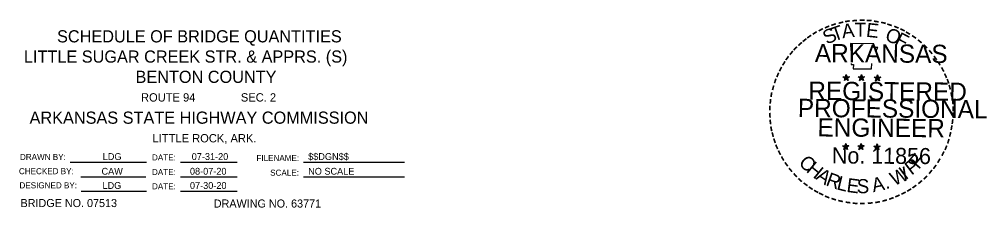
# Model space of a CAD drawing. Extents: x 1667526.8 to 1667564.8, y 551427.6 to 551446.9.
# Drawn here: x 1667548.89 to 1667564.79, y 551427.59 to 551430.69 of the extents above; entities that cross this region are included whole.
import ezdxf

# ---------------------------------------------------------------- set-up
doc = ezdxf.new("R2010")
doc.units = 0
for name, color, linetype in [('Level 4', 7, 'Continuous'), ('Level 49', 7, 'Continuous'), ('Level 50', 7, 'Continuous')]:
    doc.layers.add(name, color=color, linetype=linetype)

msp = doc.modelspace()

# ---------------------------------------------------------------- linework, layer by layer
at = {"layer": 'Level 4'}
for p, q in [((1667549.721, 551428.342), (1667550.978, 551428.342)), ((1667551.535, 551428.342), (1667552.471, 551428.342)), ((1667553.561, 551428.342), (1667555.22, 551428.342)), ((1667549.898, 551428.1), (1667550.968, 551428.1)), ((1667551.535, 551428.1), (1667552.471, 551428.1)), ((1667553.561, 551428.1), (1667555.22, 551428.1)), ((1667549.906, 551427.866), (1667550.975, 551427.866)), ((1667551.535, 551427.866), (1667552.471, 551427.866))]:
    msp.add_line(p, q, dxfattribs=at)
at = {"layer": 'Level 49'}
for p, q in [((1667562.43, 551429.747), (1667562.484, 551429.73)), ((1667562.43, 551429.747), (1667562.469, 551429.745)), ((1667562.43, 551429.747), (1667562.469, 551429.743)), ((1667562.43, 551429.747), (1667562.466, 551429.737)), ((1667562.43, 551429.747), (1667562.466, 551429.732)), ((1667562.43, 551429.747), (1667562.466, 551429.73)), ((1667562.43, 551429.747), (1667562.466, 551429.724)), ((1667562.453, 551429.685), (1667562.484, 551429.73)), ((1667562.453, 551429.685), (1667562.466, 551429.728)), ((1667562.453, 551429.685), (1667562.469, 551429.722)), ((1667562.453, 551429.685), (1667562.471, 551429.721)), ((1667562.453, 551429.685), (1667562.477, 551429.717)), ((1667562.453, 551429.685), (1667562.484, 551429.717)), ((1667562.453, 551429.685), (1667562.484, 551429.713)), ((1667562.484, 551429.787), (1667562.477, 551429.747)), ((1667562.484, 551429.787), (1667562.477, 551429.75)), ((1667562.484, 551429.787), (1667562.48, 551429.75)), ((1667562.484, 551429.73), (1667562.484, 551429.787)), ((1667562.484, 551429.787), (1667562.493, 551429.747)), ((1667562.484, 551429.787), (1667562.491, 551429.75)), ((1667562.484, 551429.787), (1667562.486, 551429.75)), ((1667562.536, 551429.747), (1667562.484, 551429.73)), ((1667562.515, 551429.684), (1667562.484, 551429.73)), ((1667562.515, 551429.684), (1667562.484, 551429.717)), ((1667562.515, 551429.684), (1667562.484, 551429.713)), ((1667562.536, 551429.747), (1667562.488, 551429.743)), ((1667562.515, 551429.684), (1667562.488, 551429.717)), ((1667562.536, 551429.747), (1667562.493, 551429.739)), ((1667562.536, 551429.747), (1667562.493, 551429.735)), ((1667562.515, 551429.684), (1667562.493, 551429.728)), ((1667562.515, 551429.684), (1667562.493, 551429.722)), ((1667562.515, 551429.684), (1667562.499, 551429.73)), ((1667562.536, 551429.747), (1667562.501, 551429.735)), ((1667562.536, 551429.747), (1667562.506, 551429.732)), ((1667562.536, 551429.747), (1667562.508, 551429.73)), ((1667562.68, 551429.745), (1667562.734, 551429.73)), ((1667562.68, 551429.745), (1667562.719, 551429.743)), ((1667562.68, 551429.745), (1667562.719, 551429.739)), ((1667562.68, 551429.745), (1667562.719, 551429.737)), ((1667562.68, 551429.745), (1667562.717, 551429.73)), ((1667562.68, 551429.745), (1667562.717, 551429.728)), ((1667562.68, 551429.745), (1667562.717, 551429.722)), ((1667562.702, 551429.684), (1667562.734, 551429.73)), ((1667562.702, 551429.684), (1667562.719, 551429.724)), ((1667562.702, 551429.684), (1667562.719, 551429.722)), ((1667562.702, 551429.684), (1667562.721, 551429.721)), ((1667562.702, 551429.684), (1667562.726, 551429.715)), ((1667562.702, 551429.684), (1667562.734, 551429.715)), ((1667562.702, 551429.684), (1667562.734, 551429.713)), ((1667562.734, 551429.784), (1667562.726, 551429.745)), ((1667562.734, 551429.784), (1667562.726, 551429.747)), ((1667562.734, 551429.784), (1667562.728, 551429.747)), ((1667562.734, 551429.73), (1667562.734, 551429.784)), ((1667562.734, 551429.784), (1667562.743, 551429.745)), ((1667562.734, 551429.784), (1667562.741, 551429.747)), ((1667562.734, 551429.784), (1667562.736, 551429.747)), ((1667562.786, 551429.745), (1667562.734, 551429.73)), ((1667562.765, 551429.684), (1667562.734, 551429.73)), ((1667562.765, 551429.684), (1667562.734, 551429.715)), ((1667562.765, 551429.684), (1667562.734, 551429.713)), ((1667562.786, 551429.745), (1667562.739, 551429.743)), ((1667562.765, 551429.684), (1667562.739, 551429.715)), ((1667562.786, 551429.745), (1667562.743, 551429.737)), ((1667562.786, 551429.745), (1667562.743, 551429.735)), ((1667562.765, 551429.684), (1667562.743, 551429.728)), ((1667562.765, 551429.684), (1667562.743, 551429.721)), ((1667562.765, 551429.684), (1667562.749, 551429.728)), ((1667562.786, 551429.745), (1667562.75, 551429.732)), ((1667562.786, 551429.745), (1667562.756, 551429.73)), ((1667562.786, 551429.745), (1667562.758, 551429.728)), ((1667562.945, 551429.743), (1667562.998, 551429.724)), ((1667562.945, 551429.743), (1667562.987, 551429.737)), ((1667562.945, 551429.743), (1667562.984, 551429.735)), ((1667562.945, 551429.743), (1667562.984, 551429.732)), ((1667562.945, 551429.743), (1667562.982, 551429.728)), ((1667562.945, 551429.743), (1667562.982, 551429.722)), ((1667562.945, 551429.743), (1667562.982, 551429.722)), ((1667562.965, 551429.682), (1667562.998, 551429.724)), ((1667562.965, 551429.682), (1667562.984, 551429.722)), ((1667562.965, 551429.682), (1667562.987, 551429.717)), ((1667562.965, 551429.682), (1667562.987, 551429.715)), ((1667562.965, 551429.682), (1667562.998, 551429.715)), ((1667562.965, 551429.682), (1667562.995, 551429.713)), ((1667562.965, 551429.682), (1667563.002, 551429.708)), ((1667562.998, 551429.78), (1667562.989, 551429.745)), ((1667562.998, 551429.78), (1667562.995, 551429.743)), ((1667562.998, 551429.78), (1667562.995, 551429.743)), ((1667562.998, 551429.724), (1667562.998, 551429.78)), ((1667562.998, 551429.78), (1667563.009, 551429.743)), ((1667562.998, 551429.78), (1667563.006, 551429.743)), ((1667562.998, 551429.78), (1667563.002, 551429.743)), ((1667563.05, 551429.743), (1667562.998, 551429.724)), ((1667563.028, 551429.682), (1667562.998, 551429.724)), ((1667563.028, 551429.682), (1667562.998, 551429.715)), ((1667563.028, 551429.682), (1667562.998, 551429.708)), ((1667563.05, 551429.743), (1667563.004, 551429.737)), ((1667563.028, 551429.682), (1667563.004, 551429.713)), ((1667563.05, 551429.743), (1667563.009, 551429.735)), ((1667563.05, 551429.743), (1667563.009, 551429.73)), ((1667563.028, 551429.682), (1667563.009, 551429.722)), ((1667563.028, 551429.682), (1667563.009, 551429.717)), ((1667563.028, 551429.682), (1667563.013, 551429.722)), ((1667563.05, 551429.743), (1667563.017, 551429.728)), ((1667563.05, 551429.743), (1667563.019, 551429.728)), ((1667563.05, 551429.743), (1667563.024, 551429.724)), ((1667562.423, 551428.611), (1667562.477, 551428.594)), ((1667562.423, 551428.611), (1667562.462, 551428.609)), ((1667562.423, 551428.611), (1667562.46, 551428.603)), ((1667562.423, 551428.611), (1667562.46, 551428.603)), ((1667562.423, 551428.611), (1667562.46, 551428.596)), ((1667562.423, 551428.611), (1667562.46, 551428.594)), ((1667562.423, 551428.611), (1667562.46, 551428.592)), ((1667562.441, 551428.553), (1667562.477, 551428.594)), ((1667562.441, 551428.553), (1667562.46, 551428.594)), ((1667562.441, 551428.553), (1667562.462, 551428.587)), ((1667562.441, 551428.553), (1667562.464, 551428.587)), ((1667562.441, 551428.553), (1667562.477, 551428.585)), ((1667562.441, 551428.553), (1667562.469, 551428.581)), ((1667562.441, 551428.553), (1667562.477, 551428.579)), ((1667562.477, 551428.651), (1667562.466, 551428.614)), ((1667562.477, 551428.651), (1667562.469, 551428.611)), ((1667562.477, 551428.651), (1667562.471, 551428.611)), ((1667562.506, 551428.55), (1667562.473, 551428.579)), ((1667562.477, 551428.594), (1667562.477, 551428.651)), ((1667562.477, 551428.651), (1667562.484, 551428.611)), ((1667562.477, 551428.651), (1667562.484, 551428.611)), ((1667562.477, 551428.651), (1667562.477, 551428.611)), ((1667562.528, 551428.611), (1667562.477, 551428.594)), ((1667562.506, 551428.55), (1667562.477, 551428.594)), ((1667562.506, 551428.55), (1667562.477, 551428.581)), ((1667562.506, 551428.55), (1667562.478, 551428.581)), ((1667562.528, 551428.611), (1667562.48, 551428.609)), ((1667562.528, 551428.611), (1667562.484, 551428.603)), ((1667562.528, 551428.611), (1667562.484, 551428.601)), ((1667562.506, 551428.55), (1667562.484, 551428.594)), ((1667562.506, 551428.55), (1667562.484, 551428.587)), ((1667562.528, 551428.611), (1667562.491, 551428.6)), ((1667562.506, 551428.55), (1667562.491, 551428.594)), ((1667562.528, 551428.611), (1667562.495, 551428.596)), ((1667562.528, 551428.611), (1667562.499, 551428.594)), ((1667562.673, 551428.611), (1667562.726, 551428.594)), ((1667562.673, 551428.611), (1667562.712, 551428.607)), ((1667562.673, 551428.611), (1667562.712, 551428.603)), ((1667562.673, 551428.611), (1667562.712, 551428.601)), ((1667562.673, 551428.611), (1667562.71, 551428.596)), ((1667562.673, 551428.611), (1667562.71, 551428.592)), ((1667562.673, 551428.611), (1667562.71, 551428.588)), ((1667562.691, 551428.55), (1667562.726, 551428.594)), ((1667562.691, 551428.55), (1667562.712, 551428.592)), ((1667562.691, 551428.55), (1667562.712, 551428.585)), ((1667562.691, 551428.55), (1667562.713, 551428.585)), ((1667562.691, 551428.55), (1667562.719, 551428.581)), ((1667562.691, 551428.55), (1667562.726, 551428.581)), ((1667562.691, 551428.55), (1667562.726, 551428.577)), ((1667562.726, 551428.648), (1667562.717, 551428.611)), ((1667562.726, 551428.648), (1667562.719, 551428.611)), ((1667562.726, 551428.648), (1667562.721, 551428.611)), ((1667562.756, 551428.55), (1667562.725, 551428.577)), ((1667562.726, 551428.594), (1667562.726, 551428.648)), ((1667562.726, 551428.648), (1667562.734, 551428.609)), ((1667562.726, 551428.648), (1667562.734, 551428.609)), ((1667562.726, 551428.648), (1667562.726, 551428.611)), ((1667562.776, 551428.609), (1667562.726, 551428.594)), ((1667562.756, 551428.55), (1667562.726, 551428.594)), ((1667562.756, 551428.55), (1667562.726, 551428.581)), ((1667562.756, 551428.55), (1667562.728, 551428.581)), ((1667562.776, 551428.609), (1667562.732, 551428.609)), ((1667562.776, 551428.609), (1667562.734, 551428.601)), ((1667562.776, 551428.609), (1667562.734, 551428.601)), ((1667562.756, 551428.55), (1667562.734, 551428.592)), ((1667562.756, 551428.55), (1667562.734, 551428.587)), ((1667562.776, 551428.609), (1667562.741, 551428.596)), ((1667562.756, 551428.55), (1667562.741, 551428.592)), ((1667562.776, 551428.609), (1667562.747, 551428.594)), ((1667562.776, 551428.609), (1667562.749, 551428.592)), ((1667562.937, 551428.607), (1667562.991, 551428.588)), ((1667562.937, 551428.607), (1667562.976, 551428.603)), ((1667562.937, 551428.607), (1667562.976, 551428.6)), ((1667562.937, 551428.607), (1667562.974, 551428.596)), ((1667562.937, 551428.607), (1667562.974, 551428.592)), ((1667562.937, 551428.607), (1667562.972, 551428.588)), ((1667562.937, 551428.607), (1667562.972, 551428.585)), ((1667562.958, 551428.546), (1667562.991, 551428.588)), ((1667562.958, 551428.546), (1667562.974, 551428.588)), ((1667562.958, 551428.546), (1667562.976, 551428.581)), ((1667562.958, 551428.546), (1667562.98, 551428.581)), ((1667562.958, 551428.546), (1667562.984, 551428.577)), ((1667562.958, 551428.546), (1667562.989, 551428.577)), ((1667562.958, 551428.546), (1667562.991, 551428.574)), ((1667562.991, 551428.646), (1667562.982, 551428.607)), ((1667562.991, 551428.646), (1667562.984, 551428.607)), ((1667562.991, 551428.646), (1667562.987, 551428.607)), ((1667563.021, 551428.546), (1667562.989, 551428.577)), ((1667563.021, 551428.546), (1667562.989, 551428.574)), ((1667562.991, 551428.588), (1667562.991, 551428.646)), ((1667562.991, 551428.646), (1667562.998, 551428.607)), ((1667562.991, 551428.646), (1667562.998, 551428.607)), ((1667562.991, 551428.646), (1667562.991, 551428.607)), ((1667563.043, 551428.607), (1667562.991, 551428.588)), ((1667563.021, 551428.546), (1667562.991, 551428.588)), ((1667563.021, 551428.546), (1667562.995, 551428.577)), ((1667563.043, 551428.607), (1667562.996, 551428.603)), ((1667563.043, 551428.607), (1667562.998, 551428.6)), ((1667563.043, 551428.607), (1667562.998, 551428.596)), ((1667563.021, 551428.546), (1667562.998, 551428.581)), ((1667563.021, 551428.546), (1667563.002, 551428.588)), ((1667563.021, 551428.546), (1667563.004, 551428.588)), ((1667563.043, 551428.607), (1667563.009, 551428.594)), ((1667563.043, 551428.607), (1667563.011, 551428.588)), ((1667563.043, 551428.607), (1667563.013, 551428.588))]:
    msp.add_line(p, q, dxfattribs=at)
for points in [[(1667562.552, 551430.294), (1667562.558, 551430.179)], [(1667562.978, 551430.179), (1667563.002, 551430.231), (1667562.932, 551430.231), (1667562.935, 551430.29), (1667562.552, 551430.294)], [(1667562.565, 551429.965), (1667562.567, 551429.95), (1667562.601, 551429.948), (1667562.595, 551429.88), (1667562.897, 551429.878), (1667562.904, 551429.965)], [(1667562.484, 551429.787), (1667562.515, 551429.684), (1667562.43, 551429.747), (1667562.536, 551429.747), (1667562.453, 551429.685), (1667562.484, 551429.787)], [(1667562.734, 551429.784), (1667562.765, 551429.684), (1667562.68, 551429.745), (1667562.786, 551429.745), (1667562.702, 551429.684), (1667562.734, 551429.784)], [(1667562.998, 551429.78), (1667563.028, 551429.682), (1667562.945, 551429.743), (1667563.05, 551429.743), (1667562.965, 551429.682), (1667562.998, 551429.78)], [(1667562.477, 551428.651), (1667562.506, 551428.55), (1667562.423, 551428.611), (1667562.528, 551428.611), (1667562.441, 551428.553), (1667562.477, 551428.651)], [(1667562.726, 551428.648), (1667562.756, 551428.55), (1667562.673, 551428.611), (1667562.776, 551428.609), (1667562.691, 551428.55), (1667562.726, 551428.648)], [(1667562.991, 551428.646), (1667563.021, 551428.546), (1667562.937, 551428.607), (1667563.043, 551428.607), (1667562.958, 551428.546), (1667562.991, 551428.646)]]:
    msp.add_lwpolyline(points, dxfattribs=at)
for centre, radius in [((1667562.483, 551429.73), 0.0258), ((1667562.483, 551429.73), 0.0234), ((1667562.483, 551429.73), 0.0217), ((1667562.483, 551429.73), 0.0199), ((1667562.483, 551429.73), 0.0173), ((1667562.483, 551429.73), 0.0161), ((1667562.483, 551429.73), 0.0149), ((1667562.483, 551429.73), 0.0128), ((1667562.483, 551429.73), 0.0112), ((1667562.483, 551429.73), 0.00931), ((1667562.483, 551429.73), 0.00743), ((1667562.483, 551429.73), 0.00554), ((1667562.483, 551429.73), 0.00444), ((1667562.483, 551429.73), 0.00216), ((1667562.733, 551429.728), 0.0258), ((1667562.733, 551429.728), 0.0234), ((1667562.733, 551429.728), 0.0217), ((1667562.733, 551429.728), 0.0199), ((1667562.733, 551429.728), 0.0173), ((1667562.733, 551429.728), 0.0161), ((1667562.733, 551429.728), 0.0149), ((1667562.733, 551429.728), 0.0128), ((1667562.733, 551429.728), 0.0112), ((1667562.733, 551429.728), 0.00931), ((1667562.733, 551429.728), 0.00743), ((1667562.733, 551429.728), 0.00554), ((1667562.733, 551429.728), 0.00444), ((1667562.733, 551429.728), 0.00216), ((1667562.998, 551429.725), 0.0258), ((1667562.998, 551429.725), 0.0234), ((1667562.998, 551429.725), 0.0217), ((1667562.998, 551429.725), 0.0199), ((1667562.998, 551429.725), 0.0173), ((1667562.998, 551429.725), 0.0161), ((1667562.998, 551429.725), 0.0149), ((1667562.998, 551429.725), 0.0128), ((1667562.998, 551429.725), 0.0112), ((1667562.998, 551429.725), 0.00931), ((1667562.998, 551429.725), 0.00743), ((1667562.998, 551429.725), 0.00554), ((1667562.998, 551429.725), 0.00444), ((1667562.998, 551429.725), 0.00216), ((1667562.475, 551428.595), 0.0258), ((1667562.475, 551428.595), 0.0234), ((1667562.475, 551428.595), 0.0217), ((1667562.475, 551428.595), 0.0199), ((1667562.475, 551428.595), 0.0173), ((1667562.475, 551428.595), 0.0161), ((1667562.475, 551428.595), 0.0149), ((1667562.475, 551428.595), 0.0128), ((1667562.475, 551428.595), 0.0112), ((1667562.475, 551428.595), 0.00931), ((1667562.475, 551428.595), 0.00743), ((1667562.475, 551428.595), 0.00554), ((1667562.475, 551428.595), 0.00444), ((1667562.475, 551428.595), 0.00216), ((1667562.725, 551428.593), 0.0258), ((1667562.725, 551428.593), 0.0234), ((1667562.725, 551428.593), 0.0217), ((1667562.725, 551428.593), 0.0199), ((1667562.725, 551428.593), 0.0173), ((1667562.725, 551428.593), 0.0161), ((1667562.725, 551428.593), 0.0149), ((1667562.725, 551428.593), 0.0128), ((1667562.725, 551428.593), 0.0112), ((1667562.725, 551428.593), 0.00931), ((1667562.725, 551428.593), 0.00743), ((1667562.725, 551428.593), 0.00554), ((1667562.725, 551428.593), 0.00444), ((1667562.725, 551428.593), 0.00216), ((1667562.99, 551428.59), 0.0258), ((1667562.99, 551428.59), 0.0234), ((1667562.99, 551428.59), 0.0217), ((1667562.99, 551428.59), 0.0199), ((1667562.99, 551428.59), 0.0173), ((1667562.99, 551428.59), 0.0161), ((1667562.99, 551428.59), 0.0149), ((1667562.99, 551428.59), 0.0128), ((1667562.99, 551428.59), 0.0112), ((1667562.99, 551428.59), 0.00931), ((1667562.99, 551428.59), 0.00743), ((1667562.99, 551428.59), 0.00554), ((1667562.99, 551428.59), 0.00444), ((1667562.99, 551428.59), 0.00216)]:
    msp.add_circle(centre, radius, dxfattribs=at)

# ---------------------------------------------------------------- texts
at = {"layer": 'Level 4'}
for s, height, rotation, p in [('SCHEDULE OF BRIDGE QUANTITIES', 0.19998, 0.0047, (1667549.507, 551430.313)), ('LITTLE SUGAR CREEK STR. & APPRS. (S)', 0.19998, 0.0047, (1667548.962, 551429.98)), ('BENTON COUNTY', 0.19998, 0.0047, (1667550.797, 551429.647)), ('ROUTE 94', 0.1369, 0.0065, (1667550.887, 551429.34)), ('SEC. 2', 0.1369, 0.0065, (1667552.529, 551429.34)), ('ARKANSAS STATE HIGHWAY COMMISSION', 0.19998, 0.0047, (1667549.055, 551428.975)), ('LITTLE ROCK, ARK.', 0.13688, 0.0065, (1667551.077, 551428.668)), ('DRAWN BY:', 0.0995, 0, (1667548.897, 551428.379)), ('LDG', 0.1123, 0.0001, (1667550.258, 551428.379)), ('DATE:', 0.0995, 0, (1667551.068, 551428.371)), ('07-31-20', 0.1123, 0.0001, (1667551.721, 551428.379)), ('FILENAME:', 0.0995, 0, (1667552.785, 551428.362)), ('$$DGN$$', 0.1123, 0.0001, (1667553.636, 551428.379)), ('CHECKED BY:', 0.09945, 0, (1667548.88, 551428.145)), ('CAW', 0.1123, 0.0001, (1667550.238, 551428.137)), ('DATE:', 0.0995, 0, (1667551.068, 551428.13)), ('08-07-20', 0.1123, 0.0001, (1667551.692, 551428.137)), ('SCALE:', 0.0995, 0, (1667553.011, 551428.12)), ('NO SCALE', 0.1123, 0.0001, (1667553.636, 551428.137)), ('DESIGNED BY:', 0.09945, 0, (1667548.889, 551427.912)), ('LDG', 0.1123, 0.0001, (1667550.254, 551427.903)), ('DATE:', 0.0995, 0, (1667551.068, 551427.896)), ('07-30-20', 0.1123, 0.0001, (1667551.692, 551427.903)), ('BRIDGE NO. 07513', 0.13261, 0, (1667548.906, 551427.604)), ('DRAWING NO. 63771', 0.13261, 0, (1667552.084, 551427.596))]:
    msp.add_text(s, height=height, rotation=rotation, dxfattribs=at).set_placement(p)
at = {"layer": 'Level 49'}
for s, height, rotation, p in [('-', 0.24, 23.9096, (1667562.157, 551430.461)), ('-', 0.24, 18.7785, (1667562.253, 551430.501)), ('-', 0.24, 13.2326, (1667562.366, 551430.536)), ('-', 0.24, 9.8217, (1667562.466, 551430.561)), ('-', 0.24, 5.4992, (1667562.577, 551430.575)), ('-', 0.24, 359.7886, (1667562.691, 551430.586)), ('-', 0.24, 357.3454, (1667562.802, 551430.583)), ('-', 0.24, 351.7641, (1667562.911, 551430.573)), ('-', 0.24, 346.8073, (1667563.021, 551430.557)), ('-', 0.24, 341.9386, (1667563.115, 551430.531)), ('-', 0.24, 35.8341, (1667561.885, 551430.302)), ('-', 0.24, 33.666, (1667561.972, 551430.361)), ('-', 0.24, 28.3942, (1667562.062, 551430.414)), ('-', 0.24, 337.4575, (1667563.224, 551430.498)), ('-', 0.24, 333.7235, (1667563.32, 551430.459)), ('-', 0.24, 329.2433, (1667563.405, 551430.414)), ('-', 0.24, 325.4651, (1667563.502, 551430.357)), ('-', 0.24, 42.5646, (1667561.748, 551430.183)), ('-', 0.24, 38.5531, (1667561.814, 551430.244)), ('ARKANSAS', 0.2998, 359.6024, (1667561.966, 551429.989)), ('-', 0.24, 320.1321, (1667563.592, 551430.294)), ('-', 0.24, 315.181, (1667563.683, 551430.22)), ('-', 0.24, 50.2166, (1667561.618, 551430.041)), ('-', 0.24, 48.0254, (1667561.679, 551430.113)), ('-', 0.24, 309.4821, (1667563.766, 551430.137)), ('-', 0.24, 57.673, (1667561.507, 551429.874)), ('-', 0.24, 53.8349, (1667561.555, 551429.956)), ('-', 0.24, 306.2546, (1667563.842, 551430.046)), ('-', 0.21, 303.2777, (1667563.916, 551429.959)), ('-', 0.24, 67.3767, (1667561.422, 551429.693)), ('-', 0.24, 62.4738, (1667561.461, 551429.784)), ('-', 0.24, 299.2708, (1667563.962, 551429.869)), ('-', 0.24, 294.2652, (1667564.01, 551429.776)), ('-', 0.24, 71.9969, (1667561.387, 551429.599)), ('REGISTERED', 0.2998, 359.6024, (1667561.859, 551429.369)), ('-', 0.24, 290.1752, (1667564.051, 551429.693)), ('-', 0.24, 80.8037, (1667561.335, 551429.386)), ('-', 0.24, 75.0634, (1667561.357, 551429.491)), ('-', 0.24, 284.7257, (1667564.082, 551429.604)), ('-', 0.24, 280.1517, (1667564.112, 551429.491)), ('-', 0.24, 84.7887, (1667561.324, 551429.282)), ('PROFESSIONAL', 0.29977, 359.6024, (1667561.687, 551429.086)), ('-', 0.24, 276.1986, (1667564.138, 551429.377)), ('-', 0.24, 88.6646, (1667561.32, 551429.177)), ('-', 0.24, 273.9325, (1667564.145, 551429.267)), ('-', 0.24, 93.7983, (1667561.324, 551429.068)), ('-', 0.24, 98.5503, (1667561.335, 551428.966)), ('ENGINEER', 0.2998, 359.6024, (1667562.01, 551428.766)), ('-', 0.24, 263.1196, (1667564.145, 551429.075)), ('-', 0.24, 269.5431, (1667564.149, 551429.175)), ('-', 0.24, 101.3173, (1667561.352, 551428.857)), ('-', 0.24, 260.5977, (1667564.132, 551428.977)), ('-', 0.24, 105.0602, (1667561.378, 551428.768)), ('-', 0.24, 108.6898, (1667561.409, 551428.675)), ('-', 0.24, 252.4705, (1667564.09, 551428.766)), ('-', 0.24, 255.365, (1667564.116, 551428.875)), ('-', 0.24, 113.6667, (1667561.446, 551428.583)), ('-', 0.24, 115.3313, (1667561.492, 551428.49)), ('No. 11856', 0.2638, 359.6024, (1667562.247, 551428.322)), ('-', 0.24, 247.4911, (1667564.057, 551428.664)), ('-', 0.24, 120.0495, (1667561.544, 551428.402)), ('-', 0.24, 238.6736, (1667563.955, 551428.461)), ('-', 0.24, 244.2221, (1667564.014, 551428.572)), ('-', 0.24, 125.4958, (1667561.605, 551428.318)), ('-', 0.24, 130.3205, (1667561.672, 551428.235)), ('-', 0.24, 233.4476, (1667563.827, 551428.281)), ('-', 0.24, 233.4476, (1667563.897, 551428.363)), ('-', 0.24, 133.8262, (1667561.75, 551428.154)), ('-', 0.24, 138.5362, (1667561.825, 551428.083)), ('-', 0.24, 220.6875, (1667563.679, 551428.119)), ('-', 0.24, 225.3677, (1667563.757, 551428.194)), ('-', 0.24, 144.2487, (1667561.912, 551428.022)), ('-', 0.24, 147.6922, (1667561.994, 551427.965)), ('-', 0.24, 151.1728, (1667562.079, 551427.917)), ('-', 0.24, 211.8515, (1667563.514, 551427.991)), ('-', 0.24, 215.3387, (1667563.594, 551428.048)), ('-', 0.24, 154.2026, (1667562.16, 551427.878)), ('-', 0.24, 158.1636, (1667562.253, 551427.837)), ('-', 0.24, 162.4007, (1667562.356, 551427.806)), ('-', 0.24, 195.0767, (1667563.143, 551427.815)), ('-', 0.24, 200.3208, (1667563.244, 551427.852)), ('-', 0.24, 203.854, (1667563.337, 551427.893)), ('-', 0.24, 206.9592, (1667563.431, 551427.939)), ('-', 0.24, 167.1579, (1667562.462, 551427.782)), ('-', 0.24, 172.7179, (1667562.577, 551427.765)), ('-', 0.24, 176.1207, (1667562.689, 551427.754)), ('-', 0.24, 181.1942, (1667562.8, 551427.758)), ('-', 0.24, 185.4191, (1667562.922, 551427.767)), ('-', 0.24, 190.8882, (1667563.033, 551427.786))]:
    msp.add_text(s, height=height, rotation=rotation, dxfattribs=at).set_placement(p)
at = {"layer": 'Level 50'}
for s, rotation, p in [('T', 19.3365, (1667562.281, 551430.324)), ('A', 6.5597, (1667562.423, 551430.381)), ('T', 0.1713, (1667562.623, 551430.407)), ('E', 353.7829, (1667562.802, 551430.407)), ('S', 25.7249, (1667562.166, 551430.272)), ('O', 338.7567, (1667563.106, 551430.351)), ('F', 332.3683, (1667563.265, 551430.287)), ('C', 314.3278, (1667561.687, 551428.322)), ('P', 37.377, (1667563.557, 551428.119)), ('F', 50.1538, (1667563.675, 551428.215)), ('H', 320.7162, (1667561.812, 551428.193)), ('A', 327.1046, (1667561.968, 551428.07)), ('W', 24.6002, (1667563.27, 551427.946)), ('I', 37.377, (1667563.459, 551428.043)), ('R', 339.8814, (1667562.134, 551427.965)), ('L', 346.2698, (1667562.314, 551427.897)), ('E', 352.6582, (1667562.48, 551427.854)), ('S', 359.0466, (1667562.654, 551427.834)), ('A', 11.8234, (1667562.928, 551427.847)), ('.', 18.2118, (1667563.135, 551427.895))]:
    msp.add_text(s, height=0.231, rotation=rotation, dxfattribs=at).set_placement(p)

doc.saveas('drawing.dxf')
